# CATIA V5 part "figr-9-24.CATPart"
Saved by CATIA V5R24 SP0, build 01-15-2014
Part number: Part2
Bounding box of the stored display mesh (mm): x -72 to 72, y -80 to 90, z -20 to 41.296
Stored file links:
  D:\KAVITA\CATIA V5-6R2014 Project_ Kavita\CATIA V5-6R2014_partfiles\Partfiles\c09_catia_v5-6r2014_prt\figr-9-24.CATPart
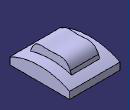
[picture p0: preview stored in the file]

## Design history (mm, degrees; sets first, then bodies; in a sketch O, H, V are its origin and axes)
Body1 (main body)
  Sketch1 on yz-plane, origin (0, 0, 0), H (0, 1, 0), V (0, 0, 1)
    arc A1 centre (5, -170) radius 190.0658 from (-80, 0) to (90, 0) cw
    point P2 (-80, 0)
    point P3 (0, 20)
    line L1 (-80, 0) -> (-80, -20)
    line L2 (-80, -20) -> (90, -20)
    line L3 (90, -20) -> (90, 0)
    coincidence: P2 H, A1 P3, P3 V
    vertical: L1 V, L3 V
    horizontal: L2 H
  Pad1: profile Sketch1, direction (1, 0, 0), length 72, mirrored extent
  Sketch2 on yz-plane, origin (0, 0, 0), H (0, 1, 0), V (0, 0, 1)
    spline S1 through (60, 20) (40, 40) (10, 40) (-10, 40) (-30, 40) (-50, 20)
  Sketch3 on zx-plane, origin (0, 0, 0), H (-1, 0, 0), V (0, 0, 1)
    line L1 (-40, 30) -> (40, 30)
    horizontal: L1 H
  Rib1: profile Sketch2, centre curve Sketch3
